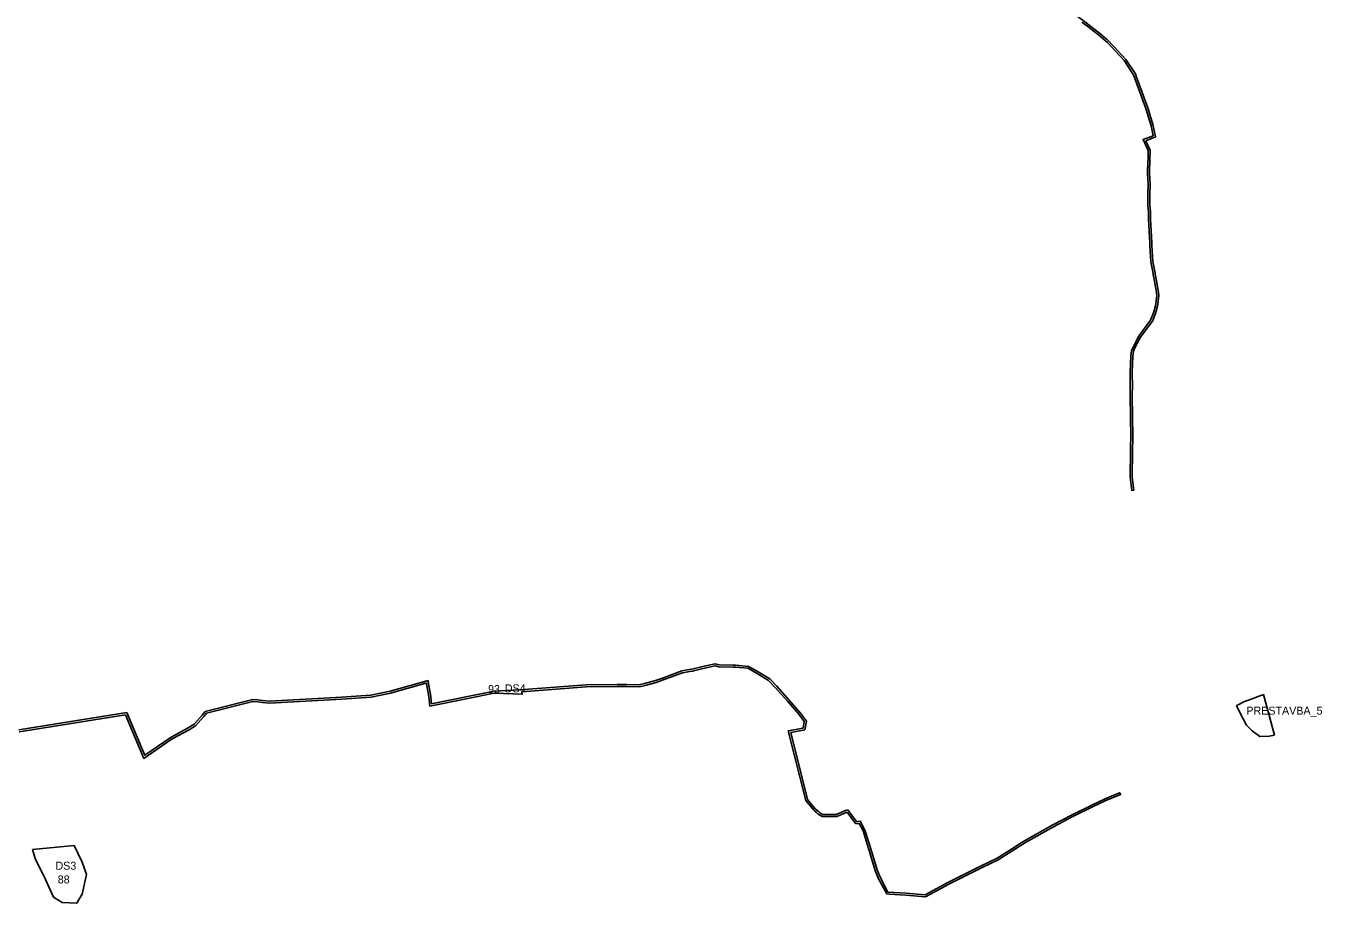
# Model space of a CAD drawing. Extents: x -477001 to -465642, y -1158278 to -1150672.
# Drawn here: x -474824 to -472881, y -1154237 to -1152921 of the extents above; entities that cross this region are included whole.
import ezdxf

# ---------------------------------------------------------------- set-up
doc = ezdxf.new("R2010")
doc.units = 0
for name, color, linetype in [('prestavba_n', 7, 'Continuous'), ('VPS_id', 7, 'Continuous'), ('VPS_n', 7, 'Continuous'), ('vyvlastneni_n', 7, 'Continuous')]:
    doc.layers.add(name, color=color, linetype=linetype)

msp = doc.modelspace()

# ---------------------------------------------------------------- linework, layer by layer
at = {"layer": 'prestavba_n'}
for p, q in [((-472968.2, -1153924.1), (-472991, -1153932.6)), ((-472951.8, -1153985.5), (-472968.2, -1153924.1)), ((-473007.3, -1153940.3), (-473009, -1153941)), ((-472997.1, -1153934.8), (-473007.3, -1153940.3)), ((-472991, -1153932.6), (-472997.1, -1153934.8)), ((-472985.3, -1153978.9), (-472973.7, -1153987.1))]:
    msp.add_line(p, q, dxfattribs=at)
for points in [[(-473009, -1153941), (-473004, -1153951.1), (-472994, -1153970.5), (-472985.3, -1153978.9)], [(-472973.7, -1153987.1), (-472959.7, -1153986.7), (-472951.8, -1153985.5)]]:
    msp.add_lwpolyline(points, dxfattribs=at)
at = {"layer": 'VPS_n'}
for p, q in [((-473203.2, -1152941.3), (-473204.7, -1152940.1)), ((-473202.5, -1152946.4), (-473196.6, -1152952.8)), ((-473163.3, -1152994.9), (-473161.4, -1153000.1)), ((-473158.8, -1152998.5), (-473160.6, -1152993.5)), ((-473161.4, -1153000.1), (-473155.8, -1153015.2)), ((-473155.8, -1153015.2), (-473144.8, -1153045.2)), ((-473133.8, -1153070.6), (-473140.9, -1153047.7)), ((-473133.7, -1153071.3), (-473133.8, -1153070.6)), ((-473130.4, -1153087.9), (-473133.7, -1153071.3)), ((-473144.8, -1153093.6), (-473132.7, -1153089)), ((-473138.3, -1153107.8), (-473144.8, -1153093.6)), ((-473132.7, -1153089), (-473130.4, -1153088.1)), ((-473130.4, -1153088.1), (-473130.4, -1153087.9)), ((-473142, -1153151.3), (-473141.6, -1153158.2)), ((-473138.6, -1153158.1), (-473139, -1153151.1)), ((-473141.6, -1153158.2), (-473141.8, -1153174.9)), ((-473142, -1153181.2), (-473142.1, -1153187.3)), ((-473141.9, -1153176.5), (-473142, -1153181.2)), ((-473141.8, -1153174.9), (-473141.9, -1153176.5)), ((-473141, -1153200.9), (-473140.7, -1153212)), ((-473134.3, -1153274.8), (-473135.7, -1153250.6)), ((-473137.3, -1153275.1), (-473134.1, -1153292.6)), ((-473131.9, -1153303.9), (-473131.3, -1153307.3)), ((-473127.5, -1153342), (-473125.4, -1153326.1)), ((-473125.4, -1153326.1), (-473126, -1153320.9)), ((-473155.6, -1153386.9), (-473164.1, -1153403.3)), ((-473165.6, -1153441.5), (-473164.5, -1153416.7)), ((-473164.5, -1153416.7), (-473163.3, -1153409.4)), ((-473168.2, -1153459.3), (-473168.5, -1153477)), ((-473168.2, -1153455.6), (-473168.2, -1153459.3)), ((-473165.1, -1153459.3), (-473165.5, -1153445)), ((-473165.5, -1153477), (-473165.1, -1153459.3)), ((-473168.5, -1153477), (-473167.6, -1153538.1)), ((-473164.6, -1153538.1), (-473165.5, -1153477)), ((-473167.6, -1153538.1), (-473167.7, -1153552.9)), ((-473164.8, -1153559.2), (-473164.6, -1153538.1)), ((-473167.7, -1153552.9), (-473167.8, -1153558)), ((-473167.8, -1153558), (-473167.8, -1153559.2)), ((-473165.3, -1153597.7), (-473164.8, -1153559.2)), ((-473163, -1153617.7), (-473165.3, -1153597.7)), ((-474221.4, -1153903.1), (-474278.4, -1153919.3)), ((-473984.2, -1153910), (-474084.1, -1153917.3)), ((-473937.5, -1153909.1), (-473984.2, -1153910)), ((-474084.1, -1153917.3), (-474122.3, -1153919.3)), ((-473984.1, -1153913), (-473937.5, -1153912.1)), ((-474673, -1153951.3), (-474835, -1153977.5)), ((-474834.5, -1153980.5), (-474674.9, -1153954.6)), ((-473657.2, -1153964.8), (-473658.9, -1153974.7)), ((-473592.9, -1154100.9), (-473591.5, -1154102.7)), ((-473568.9, -1154128.9), (-473565.3, -1154140.5)), ((-474752, -1154150.6), (-474814.4, -1154156.6)), ((-474814.4, -1154156.6), (-474810.9, -1154168.9)), ((-474810.9, -1154168.9), (-474810.2, -1154171.4)), ((-474810.2, -1154171.4), (-474795.1, -1154202)), ((-474795.1, -1154202), (-474783.1, -1154228.1)), ((-474783.1, -1154228.1), (-474770, -1154236.2)), ((-474770, -1154236.2), (-474748, -1154237.1))]:
    msp.add_line(p, q, dxfattribs=at)
for points in [[(-473221, -1152927.4), (-473239.1, -1152913.2), (-473263.2, -1152896), (-473285.7, -1152876.3)], [(-473240.9, -1152915.6), (-473232, -1152922.5), (-473222.5, -1152930), (-473216.1, -1152934.6), (-473205.2, -1152943.6), (-473202.5, -1152946.4)], [(-473204.7, -1152940.1), (-473214.3, -1152932.2), (-473221, -1152927.4)], [(-473160.6, -1152993.5), (-473175, -1152971.6), (-473192.3, -1152953), (-473203.2, -1152941.3)], [(-473196.6, -1152952.8), (-473177.4, -1152973.4), (-473163.3, -1152994.9)], [(-473140.9, -1153047.7), (-473141.8, -1153044.5), (-473141.9, -1153044.2), (-473158.8, -1152998.5)], [(-473144.8, -1153045.2), (-473136.7, -1153071.4), (-473133.8, -1153086.2)], [(-473133.8, -1153086.2), (-473148.9, -1153091.9), (-473141.3, -1153108.4), (-473141.6, -1153118.1)], [(-473139, -1153151.1), (-473139.2, -1153141.8), (-473139.3, -1153138.6), (-473138.3, -1153107.8)], [(-473141.6, -1153118.1), (-473142.3, -1153138.6), (-473142.2, -1153141.9), (-473142, -1153151.3)], [(-473139, -1153181.3), (-473138.9, -1153176.7), (-473138.8, -1153175), (-473138.6, -1153158.1)], [(-473142.1, -1153187.3), (-473142.1, -1153189.8), (-473141.5, -1153195.6), (-473141, -1153200.9)], [(-473139.1, -1153189.7), (-473139.1, -1153187.3), (-473139, -1153181.3)], [(-473135.7, -1153250.6), (-473135.9, -1153247.2), (-473137.4, -1153219.8), (-473137.7, -1153211.9), (-473138, -1153200.6), (-473138.6, -1153195.3), (-473139.1, -1153189.7)], [(-473140.7, -1153212), (-473140.4, -1153219.9), (-473138.9, -1153247.3), (-473138.7, -1153250.8), (-473137.3, -1153275.1)], [(-473126, -1153320.9), (-473128.3, -1153306.8), (-473128.9, -1153303.4), (-473131, -1153293.6), (-473131.1, -1153292.1), (-473134.3, -1153274.8)], [(-473131.3, -1153307.3), (-473128.9, -1153321.4), (-473128.4, -1153326.1), (-473130.4, -1153341.4), (-473133.2, -1153351.7), (-473137.7, -1153362.6)], [(-473134.1, -1153292.6), (-473133.9, -1153294.1), (-473131.9, -1153303.9)], [(-473153, -1153388.4), (-473151.8, -1153386.8), (-473135.1, -1153364.1), (-473130.3, -1153352.7), (-473127.5, -1153342)], [(-473137.7, -1153362.6), (-473154.2, -1153385.1), (-473155.6, -1153386.9)], [(-473164.1, -1153403.3), (-473166.2, -1153408.6), (-473167.5, -1153416.4)], [(-473163.3, -1153409.4), (-473161.3, -1153404.5), (-473153, -1153388.4)], [(-473167.5, -1153416.4), (-473168.6, -1153441.5), (-473168.5, -1153443.9)], [(-473168.5, -1153443.9), (-473168.5, -1153445.1), (-473168.2, -1153455.6)], [(-473165.5, -1153445), (-473165.5, -1153443.8), (-473165.6, -1153441.5)], [(-473167.8, -1153559.2), (-473168.3, -1153597.9), (-473166, -1153618.1), (-473163, -1153617.7)], [(-473654, -1153964.1), (-473662.9, -1153952.1), (-473679.8, -1153933), (-473698.5, -1153911.8), (-473708.8, -1153901), (-473728.8, -1153888.6), (-473740.8, -1153882.1), (-473760.2, -1153880.5), (-473764, -1153880.5), (-473785, -1153879.6), (-473791, -1153878.2), (-473804.8, -1153881.2), (-473822, -1153885.4), (-473825.6, -1153886.1), (-473829.7, -1153887), (-473840.6, -1153889), (-473869.8, -1153899.6), (-473880.2, -1153903.4), (-473896.6, -1153907.7), (-473904.6, -1153909.7), (-473923.4, -1153909.3), (-473937.5, -1153909.1)], [(-473937.5, -1153912.1), (-473923.5, -1153912.3), (-473904.3, -1153912.7), (-473895.8, -1153910.6), (-473879.3, -1153906.3), (-473868.8, -1153902.4), (-473839.8, -1153891.9), (-473829.1, -1153890), (-473824.9, -1153889.1), (-473821.3, -1153888.3), (-473804.1, -1153884.1), (-473791, -1153881.2), (-473785.5, -1153882.6), (-473764, -1153883.5), (-473760.4, -1153883.5), (-473741.7, -1153885), (-473730.3, -1153891.2), (-473710.7, -1153903.3), (-473700.7, -1153913.8), (-473682, -1153935), (-473665.2, -1153954), (-473657.2, -1153964.8)], [(-474674.9, -1153954.6), (-474654.1, -1154005), (-474647.6, -1154020.1), (-474606.4, -1153991.8), (-474604, -1153990.5), (-474579.6, -1153977.1), (-474570.3, -1153971.3), (-474557.8, -1153957.2), (-474553.8, -1153952.5), (-474483.9, -1153934.8), (-474476.8, -1153935.5), (-474469.7, -1153936.2), (-474459.2, -1153937.3), (-474359.4, -1153931.7), (-474351.3, -1153931.1), (-474306.7, -1153928.1), (-474277.7, -1153922.3), (-474224.8, -1153907.2), (-474223.9, -1153906.9)], [(-474223.9, -1153906.9), (-474223.6, -1153908.8), (-474220.9, -1153924.1), (-474219.8, -1153932.5), (-474218.7, -1153941.9)], [(-474216.1, -1153938.3), (-474217.9, -1153923.7), (-474220.6, -1153908.3), (-474221.4, -1153903.1)], [(-474278.4, -1153919.3), (-474307.1, -1153925.1), (-474351.5, -1153928.1), (-474359.6, -1153928.7), (-474459.1, -1153934.3), (-474469.4, -1153933.3), (-474476.5, -1153932.5), (-474484.1, -1153931.8), (-474555.4, -1153949.9), (-474560.1, -1153955.2), (-474572.2, -1153969), (-474581.1, -1153974.5), (-474605.5, -1153987.9), (-474608, -1153989.3), (-474646.3, -1154015.5), (-474651.3, -1154003.8), (-474673, -1153951.3)], [(-474218.7, -1153941.9), (-474161.5, -1153930.1), (-474122, -1153922.3), (-474080.1, -1153923.7), (-474080.7, -1153920.1), (-473984.1, -1153913)], [(-474122.3, -1153919.3), (-474162.1, -1153927.2), (-474216.1, -1153938.3)], [(-473591.8, -1154097.4), (-473595.2, -1154098.4), (-473609.1, -1154104.1), (-473619.9, -1154104.2), (-473629.6, -1154104.3), (-473634.5, -1154101.2), (-473636.4, -1154099.5), (-473640.1, -1154096.3), (-473646.2, -1154089.2), (-473652.2, -1154082), (-473677.5, -1153981.3), (-473656.3, -1153977.2), (-473654, -1153964.1)], [(-473658.9, -1153974.7), (-473681.2, -1153979), (-473655, -1154083.4), (-473642.8, -1154097.8), (-473642.2, -1154098.4), (-473641.3, -1154099.2), (-473638.4, -1154101.7), (-473636.3, -1154103.6), (-473630.4, -1154107.3), (-473608.5, -1154107.1), (-473594.2, -1154101.3), (-473594, -1154101.2), (-473592.9, -1154100.9)], [(-473565.3, -1154140.5), (-473562.8, -1154148.6), (-473562.8, -1154148.8), (-473560.3, -1154156.8), (-473550.3, -1154189.6), (-473546.3, -1154199.3), (-473546.2, -1154199.7), (-473533.4, -1154223.5), (-473529.9, -1154223.7), (-473504.6, -1154225.4), (-473475.1, -1154227.8), (-473440.4, -1154209), (-473391.5, -1154184.4), (-473366.1, -1154172.3), (-473325.2, -1154146.4), (-473283.2, -1154122.7), (-473255.2, -1154107.9), (-473223.7, -1154092.3), (-473204.7, -1154083.3), (-473182.8, -1154074.4), (-473184, -1154071.6), (-473186.9, -1154072.8), (-473205.9, -1154080.6), (-473225, -1154089.6), (-473256.6, -1154105.2), (-473284.6, -1154120), (-473326.8, -1154143.8), (-473334.2, -1154148.5), (-473334.2, -1154148.5), (-473340.8, -1154152.7), (-473340.8, -1154152.7), (-473367.6, -1154169.7), (-473392.9, -1154181.7), (-473441.7, -1154206.3), (-473475.8, -1154224.7), (-473504.4, -1154222.4), (-473531.6, -1154220.6), (-473543.4, -1154198.4), (-473547.5, -1154188.6), (-473559.9, -1154147.9), (-473566.2, -1154127.8)], [(-473566.2, -1154127.8), (-473573.2, -1154114.5), (-473578.8, -1154114.9), (-473589.1, -1154100.9), (-473591.8, -1154097.4)], [(-473591.5, -1154102.7), (-473580.2, -1154118), (-473575, -1154117.6), (-473568.9, -1154128.9)], [(-474748, -1154237.1), (-474745.4, -1154232.6), (-474740.3, -1154223.9), (-474733.8, -1154194.4), (-474740.2, -1154176), (-474752, -1154150.6)]]:
    msp.add_lwpolyline(points, dxfattribs=at)
at = {"layer": 'vyvlastneni_n'}
for p, q in [((-473203.2, -1152941.3), (-473204.7, -1152940.1)), ((-473202.5, -1152946.4), (-473196.6, -1152952.8)), ((-473163.3, -1152994.9), (-473161.4, -1153000.1)), ((-473158.8, -1152998.5), (-473160.6, -1152993.5)), ((-473161.4, -1153000.1), (-473155.8, -1153015.2)), ((-473155.8, -1153015.2), (-473144.8, -1153045.2)), ((-473133.8, -1153070.6), (-473140.9, -1153047.7)), ((-473133.7, -1153071.3), (-473133.8, -1153070.6)), ((-473130.4, -1153087.9), (-473133.7, -1153071.3)), ((-473144.8, -1153093.6), (-473132.7, -1153089)), ((-473138.3, -1153107.8), (-473144.8, -1153093.6)), ((-473132.7, -1153089), (-473130.4, -1153088.1)), ((-473130.4, -1153088.1), (-473130.4, -1153087.9)), ((-473142, -1153151.3), (-473141.6, -1153158.2)), ((-473138.6, -1153158.1), (-473139, -1153151.1)), ((-473141.6, -1153158.2), (-473141.8, -1153174.9)), ((-473142, -1153181.2), (-473142.1, -1153187.3)), ((-473141.9, -1153176.5), (-473142, -1153181.2)), ((-473141.8, -1153174.9), (-473141.9, -1153176.5)), ((-473141, -1153200.9), (-473140.7, -1153212)), ((-473134.3, -1153274.8), (-473135.7, -1153250.6)), ((-473137.3, -1153275.1), (-473134.1, -1153292.6)), ((-473131.9, -1153303.9), (-473131.3, -1153307.3)), ((-473127.5, -1153342), (-473125.4, -1153326.1)), ((-473125.4, -1153326.1), (-473126, -1153320.9)), ((-473155.6, -1153386.9), (-473164.1, -1153403.3)), ((-473165.6, -1153441.5), (-473164.5, -1153416.7)), ((-473164.5, -1153416.7), (-473163.3, -1153409.4)), ((-473168.2, -1153459.3), (-473168.5, -1153477)), ((-473168.2, -1153455.6), (-473168.2, -1153459.3)), ((-473165.1, -1153459.3), (-473165.5, -1153445)), ((-473165.5, -1153477), (-473165.1, -1153459.3)), ((-473168.5, -1153477), (-473167.6, -1153538.1)), ((-473164.6, -1153538.1), (-473165.5, -1153477)), ((-473167.6, -1153538.1), (-473167.7, -1153552.9)), ((-473164.8, -1153559.2), (-473164.6, -1153538.1)), ((-473167.7, -1153552.9), (-473167.8, -1153558)), ((-473167.8, -1153558), (-473167.8, -1153559.2)), ((-473165.3, -1153597.7), (-473164.8, -1153559.2)), ((-473163, -1153617.7), (-473165.3, -1153597.7)), ((-474221.4, -1153903.1), (-474278.4, -1153919.3)), ((-473984.2, -1153910), (-474084.1, -1153917.3)), ((-473937.5, -1153909.1), (-473984.2, -1153910)), ((-474084.1, -1153917.3), (-474122.3, -1153919.3)), ((-473984.1, -1153913), (-473937.5, -1153912.1)), ((-474673, -1153951.3), (-474835, -1153977.5)), ((-474834.5, -1153980.5), (-474674.9, -1153954.6)), ((-473657.2, -1153964.8), (-473658.9, -1153974.7)), ((-473592.9, -1154100.9), (-473591.5, -1154102.7)), ((-473568.9, -1154128.9), (-473565.3, -1154140.5)), ((-474752, -1154150.6), (-474814.4, -1154156.6)), ((-474814.4, -1154156.6), (-474810.9, -1154168.9)), ((-474810.9, -1154168.9), (-474810.2, -1154171.4)), ((-474810.2, -1154171.4), (-474795.1, -1154202)), ((-474795.1, -1154202), (-474783.1, -1154228.1)), ((-474783.1, -1154228.1), (-474770, -1154236.2)), ((-474770, -1154236.2), (-474748, -1154237.1))]:
    msp.add_line(p, q, dxfattribs=at)
for points in [[(-473221, -1152927.4), (-473239.1, -1152913.2), (-473263.2, -1152896), (-473285.7, -1152876.3)], [(-473240.9, -1152915.6), (-473232, -1152922.5), (-473222.5, -1152930), (-473216.1, -1152934.6), (-473205.2, -1152943.6), (-473202.5, -1152946.4)], [(-473204.7, -1152940.1), (-473214.3, -1152932.2), (-473221, -1152927.4)], [(-473160.6, -1152993.5), (-473175, -1152971.6), (-473192.3, -1152953), (-473203.2, -1152941.3)], [(-473196.6, -1152952.8), (-473177.4, -1152973.4), (-473163.3, -1152994.9)], [(-473140.9, -1153047.7), (-473141.8, -1153044.5), (-473141.9, -1153044.2), (-473158.8, -1152998.5)], [(-473144.8, -1153045.2), (-473136.7, -1153071.4), (-473133.8, -1153086.2)], [(-473133.8, -1153086.2), (-473148.9, -1153091.9), (-473141.3, -1153108.4), (-473141.6, -1153118.1)], [(-473139, -1153151.1), (-473139.2, -1153141.8), (-473139.3, -1153138.6), (-473138.3, -1153107.8)], [(-473141.6, -1153118.1), (-473142.3, -1153138.6), (-473142.2, -1153141.9), (-473142, -1153151.3)], [(-473139, -1153181.3), (-473138.9, -1153176.7), (-473138.8, -1153175), (-473138.6, -1153158.1)], [(-473142.1, -1153187.3), (-473142.1, -1153189.8), (-473141.5, -1153195.6), (-473141, -1153200.9)], [(-473139.1, -1153189.7), (-473139.1, -1153187.3), (-473139, -1153181.3)], [(-473135.7, -1153250.6), (-473135.9, -1153247.2), (-473137.4, -1153219.8), (-473137.7, -1153211.9), (-473138, -1153200.6), (-473138.6, -1153195.3), (-473139.1, -1153189.7)], [(-473140.7, -1153212), (-473140.4, -1153219.9), (-473138.9, -1153247.3), (-473138.7, -1153250.8), (-473137.3, -1153275.1)], [(-473126, -1153320.9), (-473128.3, -1153306.8), (-473128.9, -1153303.4), (-473131, -1153293.6), (-473131.1, -1153292.1), (-473134.3, -1153274.8)], [(-473131.3, -1153307.3), (-473128.9, -1153321.4), (-473128.4, -1153326.1), (-473130.4, -1153341.4), (-473133.2, -1153351.7), (-473137.7, -1153362.6)], [(-473134.1, -1153292.6), (-473133.9, -1153294.1), (-473131.9, -1153303.9)], [(-473153, -1153388.4), (-473151.8, -1153386.8), (-473135.1, -1153364.1), (-473130.3, -1153352.7), (-473127.5, -1153342)], [(-473137.7, -1153362.6), (-473154.2, -1153385.1), (-473155.6, -1153386.9)], [(-473164.1, -1153403.3), (-473166.2, -1153408.6), (-473167.5, -1153416.4)], [(-473163.3, -1153409.4), (-473161.3, -1153404.5), (-473153, -1153388.4)], [(-473167.5, -1153416.4), (-473168.6, -1153441.5), (-473168.5, -1153443.9)], [(-473168.5, -1153443.9), (-473168.5, -1153445.1), (-473168.2, -1153455.6)], [(-473165.5, -1153445), (-473165.5, -1153443.8), (-473165.6, -1153441.5)], [(-473167.8, -1153559.2), (-473168.3, -1153597.9), (-473166, -1153618.1), (-473163, -1153617.7)], [(-473654, -1153964.1), (-473662.9, -1153952.1), (-473679.8, -1153933), (-473698.5, -1153911.8), (-473708.8, -1153901), (-473728.8, -1153888.6), (-473740.8, -1153882.1), (-473760.2, -1153880.5), (-473764, -1153880.5), (-473785, -1153879.6), (-473791, -1153878.2), (-473804.8, -1153881.2), (-473822, -1153885.4), (-473825.6, -1153886.1), (-473829.7, -1153887), (-473840.6, -1153889), (-473869.8, -1153899.6), (-473880.2, -1153903.4), (-473896.6, -1153907.7), (-473904.6, -1153909.7), (-473923.4, -1153909.3), (-473937.5, -1153909.1)], [(-473937.5, -1153912.1), (-473923.5, -1153912.3), (-473904.3, -1153912.7), (-473895.8, -1153910.6), (-473879.3, -1153906.3), (-473868.8, -1153902.4), (-473839.8, -1153891.9), (-473829.1, -1153890), (-473824.9, -1153889.1), (-473821.3, -1153888.3), (-473804.1, -1153884.1), (-473791, -1153881.2), (-473785.5, -1153882.6), (-473764, -1153883.5), (-473760.4, -1153883.5), (-473741.7, -1153885), (-473730.3, -1153891.2), (-473710.7, -1153903.3), (-473700.7, -1153913.8), (-473682, -1153935), (-473665.2, -1153954), (-473657.2, -1153964.8)], [(-474674.9, -1153954.6), (-474654.1, -1154005), (-474647.6, -1154020.1), (-474606.4, -1153991.8), (-474604, -1153990.5), (-474579.6, -1153977.1), (-474570.3, -1153971.3), (-474557.8, -1153957.2), (-474553.8, -1153952.5), (-474483.9, -1153934.8), (-474476.8, -1153935.5), (-474469.7, -1153936.2), (-474459.2, -1153937.3), (-474359.4, -1153931.7), (-474351.3, -1153931.1), (-474306.7, -1153928.1), (-474277.7, -1153922.3), (-474224.8, -1153907.2), (-474223.9, -1153906.9)], [(-474223.9, -1153906.9), (-474223.6, -1153908.8), (-474220.9, -1153924.1), (-474219.8, -1153932.5), (-474218.7, -1153941.9)], [(-474216.1, -1153938.3), (-474217.9, -1153923.7), (-474220.6, -1153908.3), (-474221.4, -1153903.1)], [(-474278.4, -1153919.3), (-474307.1, -1153925.1), (-474351.5, -1153928.1), (-474359.6, -1153928.7), (-474459.1, -1153934.3), (-474469.4, -1153933.3), (-474476.5, -1153932.5), (-474484.1, -1153931.8), (-474555.4, -1153949.9), (-474560.1, -1153955.2), (-474572.2, -1153969), (-474581.1, -1153974.5), (-474605.5, -1153987.9), (-474608, -1153989.3), (-474646.3, -1154015.5), (-474651.3, -1154003.8), (-474673, -1153951.3)], [(-474218.7, -1153941.9), (-474161.5, -1153930.1), (-474122, -1153922.3), (-474080.1, -1153923.7), (-474080.7, -1153920.1), (-473984.1, -1153913)], [(-474122.3, -1153919.3), (-474162.1, -1153927.2), (-474216.1, -1153938.3)], [(-473591.8, -1154097.4), (-473595.2, -1154098.4), (-473609.1, -1154104.1), (-473619.9, -1154104.2), (-473629.6, -1154104.3), (-473634.5, -1154101.2), (-473636.4, -1154099.5), (-473640.1, -1154096.3), (-473646.2, -1154089.2), (-473652.2, -1154082), (-473677.5, -1153981.3), (-473656.3, -1153977.2), (-473654, -1153964.1)], [(-473658.9, -1153974.7), (-473681.2, -1153979), (-473655, -1154083.4), (-473642.8, -1154097.8), (-473642.2, -1154098.4), (-473641.3, -1154099.2), (-473638.4, -1154101.7), (-473636.3, -1154103.6), (-473630.4, -1154107.3), (-473608.5, -1154107.1), (-473594.2, -1154101.3), (-473594, -1154101.2), (-473592.9, -1154100.9)], [(-473565.3, -1154140.5), (-473562.8, -1154148.6), (-473562.8, -1154148.8), (-473560.3, -1154156.8), (-473550.3, -1154189.6), (-473546.3, -1154199.3), (-473546.2, -1154199.7), (-473533.4, -1154223.5), (-473529.9, -1154223.7), (-473504.6, -1154225.4), (-473475.1, -1154227.8), (-473440.4, -1154209), (-473391.5, -1154184.4), (-473366.1, -1154172.3), (-473325.2, -1154146.4), (-473283.2, -1154122.7), (-473255.2, -1154107.9), (-473223.7, -1154092.3), (-473204.7, -1154083.3), (-473182.8, -1154074.4), (-473184, -1154071.6), (-473186.9, -1154072.8), (-473205.9, -1154080.6), (-473225, -1154089.6), (-473256.6, -1154105.2), (-473284.6, -1154120), (-473326.8, -1154143.8), (-473334.2, -1154148.5), (-473334.2, -1154148.5), (-473340.8, -1154152.7), (-473340.8, -1154152.7), (-473367.6, -1154169.7), (-473392.9, -1154181.7), (-473441.7, -1154206.3), (-473475.8, -1154224.7), (-473504.4, -1154222.4), (-473531.6, -1154220.6), (-473543.4, -1154198.4), (-473547.5, -1154188.6), (-473559.9, -1154147.9), (-473566.2, -1154127.8)], [(-473566.2, -1154127.8), (-473573.2, -1154114.5), (-473578.8, -1154114.9), (-473589.1, -1154100.9), (-473591.8, -1154097.4)], [(-473591.5, -1154102.7), (-473580.2, -1154118), (-473575, -1154117.6), (-473568.9, -1154128.9)], [(-474748, -1154237.1), (-474745.4, -1154232.6), (-474740.3, -1154223.9), (-474733.8, -1154194.4), (-474740.2, -1154176), (-474752, -1154150.6)]]:
    msp.add_lwpolyline(points, dxfattribs=at)

# ---------------------------------------------------------------- texts
at = {"layer": 'prestavba_n'}
msp.add_text('PRESTAVBA_5', height=12, dxfattribs=at).set_placement((-472994.1, -1153954.5))
at = {"layer": 'VPS_id'}
for s, p in [('93', (-474131.4, -1153922.2)), ('88', (-474776.7, -1154207.7))]:
    msp.add_text(s, height=12, dxfattribs=at).set_placement(p)
at = {"layer": 'VPS_n'}
for s, p in [('DS4', (-474106.2, -1153921.1)), ('DS3', (-474780.1, -1154187.1))]:
    msp.add_text(s, height=12, dxfattribs=at).set_placement(p)

doc.saveas('drawing.dxf')
